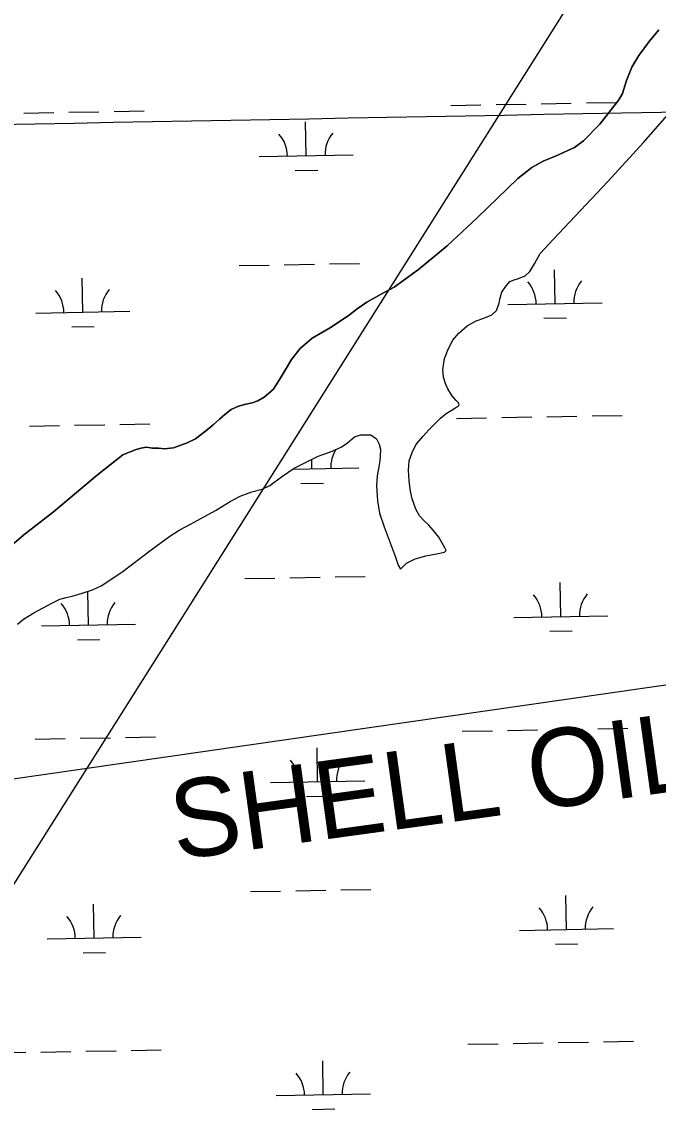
# Model space of a CAD drawing. Extents: x 3925854 to 3964121, y 224593 to 250589.
# Drawn here: x 3946120 to 3946796, y 235324 to 236486 of the extents above; entities that cross this region are included whole.
import ezdxf

# ---------------------------------------------------------------- set-up
doc = ezdxf.new("R2010")
doc.units = 0
for name, color, linetype in [('V-GRID-MAJR', 7, 'Continuous'), ('V-TOPO-SHOR', 7, 'Continuous'), ('V-UTIL-IDEN', 7, 'Continuous'), ('V-UTIL-LINE', 7, 'Continuous'), ('V-WETL-SWMP', 7, 'Continuous')]:
    doc.layers.add(name, color=color, linetype=linetype)

msp = doc.modelspace()

# ---------------------------------------------------------------- linework, layer by layer
at = {"layer": 'V-GRID-MAJR'}
msp.add_spline([(3930006.603, 236087.686), (3935327.129, 236182.494), (3940647.643, 236278.076), (3945968.142, 236374.431), (3951288.627, 236471.56), (3956609.098, 236569.464), (3961929.554, 236668.141), (3961929.555, 236668.141)], degree=3, dxfattribs=at)
at = {"layer": 'V-TOPO-SHOR'}
for points in [[(3946796.986, 236477.359), (3946787.025, 236464.897), (3946775.808, 236450.176), (3946768.47, 236437.679), (3946762.858, 236423.408), (3946758.477, 236409.646), (3946754.539, 236402.875), (3946734.608, 236377.251), (3946717.051, 236359.292), (3946707.511, 236352.244), (3946699.769, 236348.849), (3946688.153, 236343.579), (3946674.258, 236337.816), (3946662.097, 236330.98), (3946647.246, 236319.282), (3946604.013, 236277.697), (3946572.128, 236247.682), (3946541.883, 236222.719), (3946515.916, 236203.82), (3946501.294, 236195.968), (3946487.017, 236187.935), (3946476.429, 236180.903), (3946468.472, 236174.535), (3946449.057, 236161.5), (3946428.956, 236149.519), (3946416.046, 236138.847), (3946406.965, 236126.897), (3946401.241, 236117.349), (3946393.731, 236105.03), (3946387.3, 236095.145), (3946377.744, 236086.875), (3946371.223, 236083.113), (3946364.899, 236081.097), (3946358.233, 236079.611), (3946350.682, 236077.438), (3946342.584, 236073.696), (3946336.043, 236068.535), (3946330.382, 236063.712), (3946323.476, 236057.507), (3946315.341, 236050.791), (3946304.739, 236042.71), (3946296.109, 236038.276), (3946281.347, 236033.223), (3946271.883, 236031.95), (3946265.421, 236032.736), (3946259.3, 236032.818), (3946252.664, 236033.778)], [(3946497.017, 236042.853), (3946499.911, 236036.869), (3946501.24, 236031.601), (3946501.136, 236023.733), (3946500.728, 236019.365), (3946499.594, 236012.907), (3946497.718, 236003.31), (3946497.052, 235992.822), (3946498.24, 235976.889), (3946500.165, 235963.743), (3946505.398, 235949.329), (3946516.879, 235918.04), (3946520.076, 235908.551), (3946522.642, 235904.144), (3946529.026, 235910.706), (3946538.358, 235915.306), (3946549.594, 235918.306), (3946560.819, 235920.432), (3946569.238, 235922.242), (3946571.188, 235924.143), (3946569.652, 235926.961), (3946563.328, 235938.239), (3946557.479, 235945.665), (3946552.649, 235950.802), (3946547.294, 235955.946), (3946542.809, 235960.728), (3946539.057, 235967.952), (3946535.004, 235978.849), (3946533.359, 235986.918), (3946531.758, 235997.961), (3946531.035, 236009.342), (3946531.688, 236019.127), (3946534.955, 236028.005), (3946539.09, 236036.349), (3946546.2, 236045.001), (3946552.592, 236052.088), (3946559.506, 236058.993), (3946565.177, 236064.517), (3946571.016, 236069.512), (3946576.484, 236072.938), (3946581.422, 236075.846), (3946583.535, 236077.042), (3946584.776, 236078.251), (3946584.963, 236079.123), (3946584.801, 236080), (3946584.113, 236080.884), (3946581.872, 236083.537), (3946579.462, 236086.369), (3946576.879, 236089.552), (3946572.767, 236095.902), (3946570.727, 236100.478), (3946568.38, 236108.207), (3946567.61, 236116.09), (3946569.519, 236128.134), (3946573.506, 236138.577), (3946578.348, 236147.434), (3946584.744, 236154.87), (3946593.593, 236162.626), (3946603.108, 236167.922), (3946611.021, 236170.966), (3946619.816, 236174.523), (3946624.6, 236179.182), (3946627.326, 236186.844), (3946628.257, 236191.204), (3946630.455, 236198.522), (3946634.205, 236204.246), (3946638.827, 236209.958), (3946643.572, 236211.643), (3946647.085, 236212.647), (3946655, 236215.864), (3946660.137, 236220.695), (3946664.966, 236228.678), (3946671.059, 236239.619), (3946685.081, 236255.001), (3946742.923, 236316.335), (3946780.729, 236357.467), (3946836.5, 236421.102)], [(3946115.852, 235845.688), (3946122.043, 235850.853), (3946132.981, 235857.882), (3946152.185, 235868.122), (3946160.638, 235872.384), (3946167.484, 235874.217), (3946173.626, 235875.536), (3946183.456, 235878.202), (3946195.404, 235882.243), (3946204.731, 235886.318), (3946226.616, 235900.898), (3946257.895, 235924.796), (3946277.505, 235939.232), (3946287.558, 235945.571), (3946299.365, 235952.061), (3946311.342, 235958.199), (3946326.147, 235966.575), (3946341.841, 235975.99), (3946352.414, 235981.796), (3946364.543, 235986.185), (3946375.606, 235989.361), (3946383.876, 235993.099), (3946396.067, 236002.208), (3946409.836, 236011.648), (3946435.022, 236024.433), (3946448.201, 236028.982), (3946459.635, 236033.727), (3946466.173, 236038.54), (3946473.777, 236044.735), (3946480.279, 236047.099), (3946491.121, 236046.781), (3946497.017, 236042.853)], [(3946252.664, 236033.778), (3946246.705, 236032.81), (3946240.735, 236031.139), (3946227.542, 236025.541), (3946200.674, 236004.555), (3946153.793, 235965.117), (3946122.33, 235940.521), (3946109.593, 235929.842)]]:
    msp.add_lwpolyline(points, dxfattribs=at)
at = {"layer": 'V-UTIL-LINE'}
msp.add_line((3947949.336, 238483.295), (3945978.591, 235358.555), dxfattribs=at)
msp.add_lwpolyline([(3951084.343, 243921.319), (3947981.77, 238738.296), (3948844.302, 237642.921), (3949260.796, 236134.673), (3945931.135, 235655.081), (3945509.058, 234777.685), (3942603.575, 230254.808)], dxfattribs=at)
at = {"layer": 'V-WETL-SWMP'}
for p, q in [((3946122.305, 236388.823), (3946154.3, 236389.405)), ((3946170.297, 236389.695), (3946202.292, 236390.277)), ((3946218.289, 236390.568), (3946250.284, 236391.15)), ((3946576.138, 236397.075), (3946608.133, 236397.657)), ((3946624.13, 236397.948), (3946656.125, 236398.529)), ((3946672.122, 236398.82), (3946704.117, 236399.402)), ((3946720.114, 236399.693), (3946752.109, 236400.275)), ((3946422.494, 236343.531), (3946421.839, 236379.525)), ((3946372.502, 236342.622), (3946472.486, 236344.44)), ((3946410.776, 236327.884), (3946434.772, 236328.32)), ((3946351.197, 236226.783), (3946383.191, 236227.365)), ((3946399.189, 236227.656), (3946431.183, 236228.238)), ((3946447.181, 236228.529), (3946479.175, 236229.11)), ((3946686.829, 236186.448), (3946686.175, 236222.443)), ((3946185.004, 236177.324), (3946184.35, 236213.318)), ((3946636.838, 236185.539), (3946736.821, 236187.357)), ((3946135.013, 236176.415), (3946234.996, 236178.233)), ((3946675.112, 236170.802), (3946699.108, 236171.238)), ((3946173.287, 236161.677), (3946197.283, 236162.113)), ((3946582.186, 236064.455), (3946614.181, 236065.037)), ((3946630.178, 236065.328), (3946662.173, 236065.909)), ((3946678.17, 236066.2), (3946710.165, 236066.782)), ((3946726.162, 236067.073), (3946758.157, 236067.655)), ((3946128.353, 236056.203), (3946160.348, 236056.785)), ((3946176.345, 236057.075), (3946208.34, 236057.657)), ((3946224.337, 236057.948), (3946256.332, 236058.53)), ((3946428.542, 236010.911), (3946428.358, 236021.051)), ((3946408.222, 236010.541), (3946478.534, 236011.82)), ((3946416.824, 235995.264), (3946440.82, 235995.7)), ((3946357.245, 235894.163), (3946389.239, 235894.745)), ((3946405.237, 235895.036), (3946437.231, 235895.618)), ((3946453.229, 235895.909), (3946485.223, 235896.49)), ((3946692.877, 235853.828), (3946692.223, 235889.822)), ((3946191.052, 235844.704), (3946190.401, 235880.551)), ((3946141.061, 235843.795), (3946241.044, 235845.613)), ((3946642.886, 235852.919), (3946742.869, 235854.737)), ((3946681.16, 235838.182), (3946705.156, 235838.618)), ((3946179.335, 235829.057), (3946203.331, 235829.493)), ((3946588.234, 235731.835), (3946620.229, 235732.417)), ((3946636.226, 235732.707), (3946668.221, 235733.289)), ((3946684.218, 235733.58), (3946716.213, 235734.162)), ((3946732.21, 235734.453), (3946764.205, 235735.035)), ((3946134.401, 235723.583), (3946166.396, 235724.165)), ((3946182.393, 235724.455), (3946214.388, 235725.037)), ((3946230.385, 235725.328), (3946262.38, 235725.91)), ((3946434.59, 235678.291), (3946433.935, 235714.285)), ((3946384.598, 235677.382), (3946484.582, 235679.2)), ((3946422.872, 235662.644), (3946446.869, 235663.08)), ((3946363.293, 235561.543), (3946395.287, 235562.125)), ((3946411.285, 235562.416), (3946443.279, 235562.998)), ((3946459.277, 235563.289), (3946491.272, 235563.87)), ((3946698.925, 235521.208), (3946698.271, 235557.202)), ((3946197.1, 235512.084), (3946196.446, 235548.078)), ((3946648.934, 235520.299), (3946748.917, 235522.117)), ((3946147.109, 235511.175), (3946247.092, 235512.993)), ((3946185.383, 235496.437), (3946209.379, 235496.873)), ((3946687.208, 235505.562), (3946711.204, 235505.998)), ((3946738.258, 235401.833), (3946770.253, 235402.415)), ((3946092.457, 235390.09), (3946124.452, 235390.672)), ((3946140.449, 235390.963), (3946172.444, 235391.545)), ((3946188.441, 235391.835), (3946220.436, 235392.417)), ((3946236.433, 235392.708), (3946268.428, 235393.29)), ((3946594.282, 235399.215), (3946626.277, 235399.797)), ((3946642.274, 235400.087), (3946674.269, 235400.669)), ((3946690.266, 235400.96), (3946722.261, 235401.542)), ((3946440.638, 235345.671), (3946439.984, 235381.665)), ((3946390.646, 235344.762), (3946490.63, 235346.58)), ((3946428.921, 235330.024), (3946452.917, 235330.46))]:
    msp.add_line(p, q, dxfattribs=at)
for points in [[(3946416.045, 236138.846), (3946428.956, 236149.52), (3946449.057, 236161.499), (3946468.472, 236174.536), (3946476.429, 236180.903), (3946487.018, 236187.935), (3946501.294, 236195.967), (3946515.917, 236203.82), (3946541.883, 236222.718), (3946572.127, 236247.682), (3946604.013, 236277.697), (3946647.247, 236319.282), (3946662.096, 236330.981), (3946674.257, 236337.817), (3946688.153, 236343.58), (3946699.769, 236348.849), (3946707.511, 236352.245), (3946717.05, 236359.291), (3946734.607, 236377.251), (3946754.539, 236402.876), (3946758.477, 236409.646), (3946762.858, 236423.408), (3946768.47, 236437.678), (3946775.808, 236450.176), (3946787.024, 236464.896), (3946796.985, 236477.359)], [(3946611.021, 236170.966), (3946619.815, 236174.523), (3946624.6, 236179.183), (3946627.325, 236186.844), (3946628.258, 236191.205), (3946630.454, 236198.522), (3946634.204, 236204.245), (3946638.828, 236209.957), (3946643.573, 236211.643), (3946647.085, 236212.646), (3946655, 236215.865), (3946660.137, 236220.695), (3946664.966, 236228.678), (3946671.058, 236239.618), (3946685.082, 236255.001), (3946742.923, 236316.334), (3946780.728, 236357.466), (3946836.501, 236421.102)], [(3946115.851, 235845.688), (3946122.042, 235850.854), (3946132.981, 235857.881), (3946152.185, 235868.122), (3946160.638, 235872.383), (3946167.484, 235874.217), (3946173.625, 235875.535), (3946183.456, 235878.203), (3946195.405, 235882.243), (3946204.73, 235886.318), (3946226.615, 235900.897), (3946257.895, 235924.797), (3946277.504, 235939.232), (3946287.559, 235945.571), (3946299.365, 235952.062), (3946311.342, 235958.2), (3946326.147, 235966.576), (3946341.841, 235975.989), (3946352.414, 235981.796), (3946364.542, 235986.184), (3946375.605, 235989.361), (3946383.876, 235993.099), (3946396.067, 236002.209), (3946409.837, 236011.648), (3946435.022, 236024.434), (3946448.202, 236028.982), (3946459.635, 236033.728), (3946466.172, 236038.54), (3946473.776, 236044.736), (3946480.28, 236047.099), (3946491.121, 236046.781), (3946497.017, 236042.854), (3946499.911, 236036.868), (3946501.241, 236031.602), (3946501.136, 236023.732), (3946500.729, 236019.364), (3946499.593, 236012.907), (3946497.717, 236003.31), (3946497.053, 235992.823), (3946498.241, 235976.889), (3946500.166, 235963.743), (3946505.398, 235949.33), (3946516.878, 235918.04), (3946520.076, 235908.551), (3946522.642, 235904.144), (3946529.026, 235910.706), (3946538.358, 235915.306), (3946549.594, 235918.306), (3946560.818, 235920.431), (3946569.238, 235922.243), (3946571.188, 235924.142), (3946569.651, 235926.961), (3946563.328, 235938.24), (3946557.479, 235945.665), (3946552.649, 235950.802), (3946547.294, 235955.946), (3946542.809, 235960.729), (3946539.057, 235967.951), (3946535.003, 235978.85), (3946533.36, 235986.919), (3946531.758, 235997.961), (3946531.034, 236009.341), (3946531.688, 236019.128), (3946534.955, 236028.006), (3946539.089, 236036.348), (3946546.201, 236045.001), (3946552.592, 236052.088), (3946559.506, 236058.994), (3946565.177, 236064.516), (3946571.016, 236069.512), (3946576.484, 236072.938), (3946581.421, 236075.846), (3946583.536, 236077.043), (3946584.777, 236078.251), (3946584.963, 236079.123), (3946584.8, 236080), (3946584.112, 236080.884), (3946581.873, 236083.537), (3946579.461, 236086.368), (3946576.88, 236089.551), (3946572.766, 236095.903), (3946570.727, 236100.478), (3946568.381, 236108.207), (3946567.61, 236116.089), (3946569.519, 236128.134), (3946573.506, 236138.577), (3946578.347, 236147.434), (3946584.743, 236154.871), (3946593.592, 236162.626), (3946603.109, 236167.922), (3946611.021, 236170.966)], [(3946109.593, 235929.843), (3946122.329, 235940.52), (3946153.793, 235965.118), (3946200.673, 236004.555), (3946227.541, 236025.541), (3946240.735, 236031.139), (3946246.705, 236032.809), (3946252.665, 236033.779), (3946259.3, 236032.817), (3946265.421, 236032.735), (3946271.883, 236031.95), (3946281.347, 236033.224), (3946296.108, 236038.276), (3946304.738, 236042.71), (3946315.341, 236050.791), (3946323.477, 236057.506), (3946330.382, 236063.712), (3946336.043, 236068.535), (3946342.584, 236073.696), (3946350.681, 236077.437), (3946358.232, 236079.611), (3946364.899, 236081.097), (3946371.223, 236083.112), (3946377.745, 236086.874), (3946387.301, 236095.144), (3946393.73, 236105.03), (3946401.24, 236117.35), (3946406.965, 236126.896), (3946416.045, 236138.846)]]:
    msp.add_lwpolyline(points, dxfattribs=at)
for centre, start, end in [((3946367.251, 236343.001), 0.269879, 41.813537), ((3946477.719, 236345.01), 140.269876, 181.813534), ((3946631.587, 236185.919), 0.269879, 41.813537), ((3946742.054, 236187.928), 140.269876, 181.813534), ((3946129.762, 236176.794), 0.269879, 41.813537), ((3946240.229, 236178.803), 140.269876, 181.813534), ((3946483.767, 236012.39), 147.294843, 181.813534), ((3946373.299, 236010.381), 0.269879, 0.618253), ((3946135.81, 235844.174), 0.269879, 41.813537), ((3946246.278, 235846.183), 140.269876, 181.813534), ((3946637.635, 235853.299), 0.269879, 41.813537), ((3946748.103, 235855.307), 140.269876, 181.813534), ((3946379.348, 235677.761), 0.269879, 41.813537), ((3946489.815, 235679.77), 140.269876, 181.813534), ((3946643.683, 235520.679), 0.269879, 41.813537), ((3946754.151, 235522.687), 140.269876, 181.813534), ((3946141.858, 235511.554), 0.269879, 41.813537), ((3946252.326, 235513.563), 140.269876, 181.813534), ((3946385.396, 235345.141), 0.269879, 41.813537), ((3946495.863, 235347.15), 140.269876, 181.813534)]:
    msp.add_arc(centre, 35.246, start, end, dxfattribs=at)

# ---------------------------------------------------------------- texts
at = {"layer": 'V-UTIL-IDEN'}
msp.add_text('SHELL OIL CO.', height=82.99983, rotation=7.847375, dxfattribs=at).set_placement((3946284.185, 235595.034))

doc.saveas('drawing.dxf')
